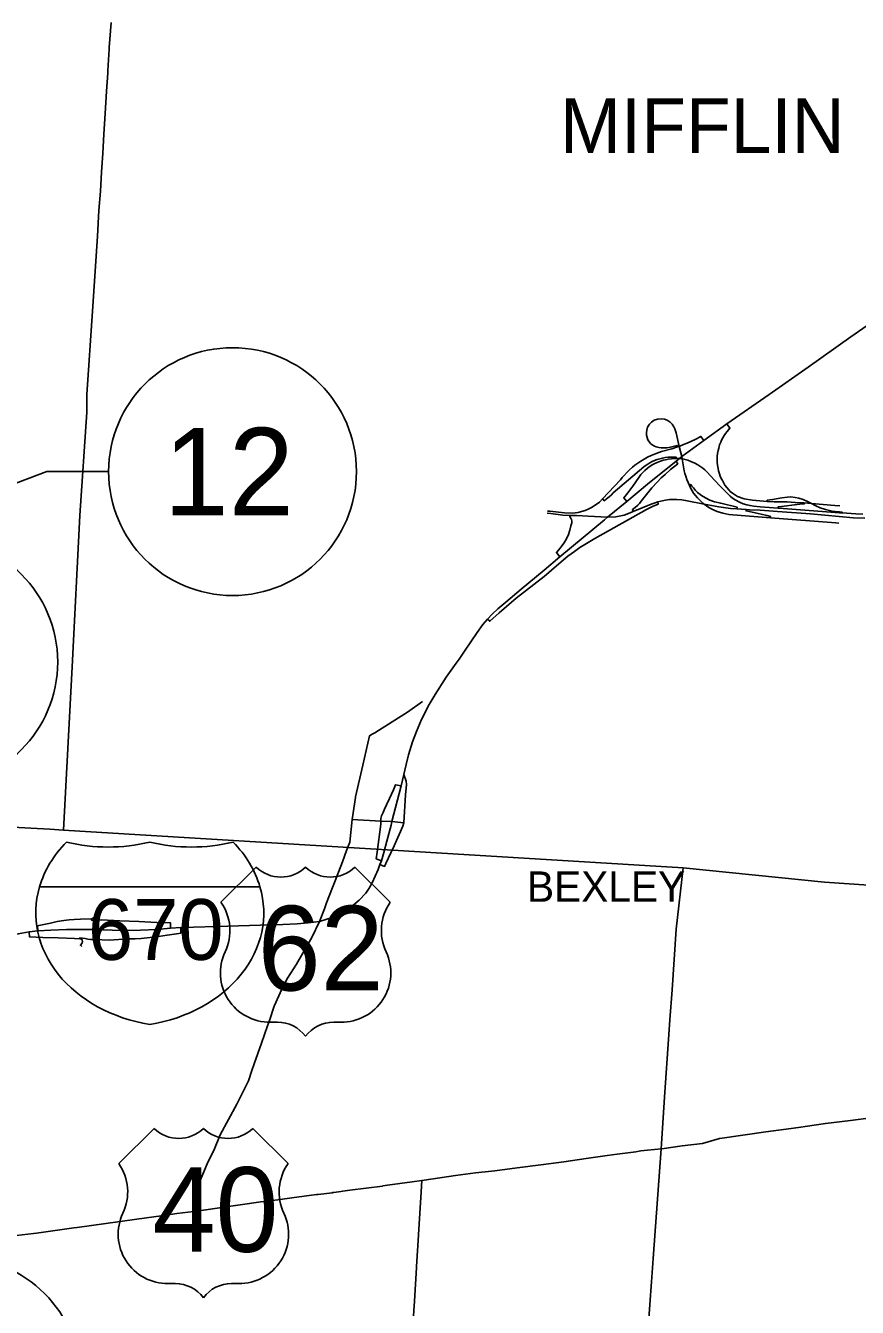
# Model space of a CAD drawing. Extents: x -1146 to -445, y -1283 to -822.
# Drawn here: x -856.5 to -822.3, y -1056.6 to -1003.9 of the extents above; entities that cross this region are included whole.
import ezdxf

# ---------------------------------------------------------------- set-up
doc = ezdxf.new("R2010")
doc.units = 0
for name, color, linetype in [('Default', 7, 'Continuous'), ('GM_X_Corporation_Text', 7, 'Continuous'), ('GM_X_Interchange_Ramps', 7, 'Continuous'), ('GM_X_Interstate_Route', 7, 'Continuous'), ('GM_X_Interstate_Shield', 7, 'Continuous'), ('GM_X_State_Route', 7, 'Continuous'), ('GM_X_Township', 7, 'Continuous'), ('GM_X_Township_Text', 7, 'Continuous'), ('GM_X_US_Route', 7, 'Continuous'), ('GM_X_US_Shield', 7, 'Continuous')]:
    doc.layers.add(name, color=color, linetype=linetype)

msp = doc.modelspace()

# ---------------------------------------------------------------- linework, layer by layer
at = {"layer": 'Default'}
msp.add_lwpolyline([(-853.091, -1022.261), (-855.638, -1022.261), (-873.197, -1028.924)], dxfattribs=at)
for centre in [(-847.997, -1022.261), (-860.28, -1030.089), (-859.326, -1059.664)]:
    msp.add_circle(centre, 5.094, dxfattribs=at)
at = {"layer": 'GM_X_Interchange_Ramps'}
for points in [[(-829.697, -1021.245), (-829.718, -1021.181), (-829.824, -1021.214), (-829.986, -1021.252), (-830.143, -1021.278), (-830.258, -1021.287), (-830.371, -1021.287), (-830.469, -1021.266), (-830.579, -1021.24), (-830.654, -1021.209), (-830.74, -1021.157), (-830.808, -1021.099), (-830.854, -1021.047), (-830.918, -1020.949), (-830.954, -1020.864), (-830.978, -1020.759), (-830.983, -1020.655), (-830.97, -1020.552), (-830.931, -1020.434), (-830.861, -1020.316), (-830.776, -1020.227), (-830.663, -1020.151), (-830.519, -1020.099), (-830.374, -1020.085), (-830.236, -1020.105), (-830.127, -1020.146), (-830.011, -1020.222), (-829.924, -1020.311), (-829.859, -1020.414), (-829.807, -1020.507), (-829.758, -1020.66), (-829.631, -1021.224), (-829.525, -1021.642), (-829.507, -1021.736), (-829.429, -1022.227), (-829.397, -1022.339), (-829.361, -1022.444), (-829.318, -1022.587), (-829.269, -1022.708), (-829.224, -1022.804), (-829.208, -1022.835), (-829.151, -1022.961), (-829.039, -1023.151), (-828.885, -1023.343), (-828.747, -1023.479), (-828.601, -1023.598), (-828.453, -1023.714), (-828.291, -1023.806), (-828.074, -1023.896), (-827.837, -1023.975), (-827.596, -1024.023), (-827.431, -1024.043), (-825.876, -1024.161), (-823.189, -1024.362), (-823.076, -1024.374)], [(-823.024, -1023.667), (-823.232, -1023.651), (-824.194, -1023.577), (-824.498, -1023.549), (-824.859, -1023.525), (-825.196, -1023.508), (-825.731, -1023.506), (-826.014, -1023.495), (-826.619, -1023.435), (-826.969, -1023.375), (-827.242, -1023.282), (-827.444, -1023.153), (-827.533, -1023.075), (-827.586, -1023.025), (-827.598, -1023.013), (-827.68, -1022.915), (-827.752, -1022.816), (-827.802, -1022.737), (-827.86, -1022.633), (-827.906, -1022.54), (-827.946, -1022.444), (-827.978, -1022.352), (-828.012, -1022.235), (-828.035, -1022.134), (-828.058, -1021.992), (-828.059, -1021.981), (-828.067, -1021.885), (-828.071, -1021.757), (-828.066, -1021.638), (-828.054, -1021.52), (-828.032, -1021.395), (-828.008, -1021.294), (-827.97, -1021.166), (-827.927, -1021.055), (-827.888, -1020.966), (-827.84, -1020.874), (-827.782, -1020.775), (-827.725, -1020.689), (-827.667, -1020.612), (-827.548, -1020.47), (-827.677, -1020.291)], [(-828.622, -1020.976), (-828.738, -1020.815), (-828.948, -1020.925), (-829.154, -1021.024), (-829.307, -1021.092), (-829.457, -1021.148), (-829.631, -1021.224), (-829.697, -1021.245), (-829.941, -1021.32), (-830.362, -1021.433), (-830.581, -1021.512), (-830.787, -1021.602), (-830.938, -1021.673), (-831.075, -1021.747), (-831.214, -1021.83), (-831.331, -1021.908), (-831.455, -1021.999), (-831.556, -1022.08), (-831.689, -1022.197), (-831.791, -1022.298), (-831.913, -1022.43), (-831.979, -1022.507), (-832.049, -1022.597), (-832.792, -1023.38), (-832.912, -1023.514), (-833.044, -1023.617), (-833.238, -1023.743), (-833.38, -1023.804), (-833.506, -1023.855), (-833.656, -1023.898), (-833.787, -1023.939), (-834.037, -1023.965), (-834.352, -1023.95), (-834.954, -1023.892), (-835.054, -1023.884)], [(-829.743, -1021.723), (-829.752, -1021.668), (-829.85, -1021.663), (-829.973, -1021.663), (-830.091, -1021.67), (-830.212, -1021.685), (-830.324, -1021.706), (-830.426, -1021.731), (-830.534, -1021.764), (-830.643, -1021.805), (-830.741, -1021.849), (-830.841, -1021.901), (-830.929, -1021.953), (-830.994, -1021.996), (-831.091, -1022.067), (-832.345, -1023.139), (-832.42, -1023.21), (-832.519, -1023.298), (-832.618, -1023.381), (-832.715, -1023.456), (-832.792, -1023.38)], [(-822.084, -1024.014), (-822.37, -1023.999), (-822.931, -1023.961), (-823.042, -1023.95), (-825.533, -1023.765), (-825.563, -1023.762), (-826.307, -1023.703), (-826.568, -1023.678), (-826.718, -1023.658), (-826.857, -1023.622), (-826.998, -1023.579), (-827.149, -1023.518), (-827.334, -1023.421), (-827.444, -1023.348), (-827.544, -1023.267), (-827.668, -1023.145), (-827.826, -1022.979), (-827.971, -1022.827), (-828.154, -1022.636), (-828.341, -1022.441), (-828.485, -1022.283), (-828.58, -1022.19), (-828.666, -1022.12), (-828.75, -1022.058), (-828.869, -1021.986), (-828.987, -1021.914), (-829.152, -1021.847), (-829.284, -1021.795), (-829.44, -1021.749), (-829.507, -1021.736), (-829.625, -1021.723), (-829.743, -1021.723), (-829.832, -1021.723), (-829.944, -1021.737), (-830.081, -1021.751), (-830.197, -1021.771), (-830.297, -1021.795), (-830.404, -1021.827), (-830.546, -1021.884), (-830.634, -1021.928), (-830.723, -1021.972), (-830.827, -1022.032), (-830.939, -1022.12), (-831.046, -1022.213), (-831.114, -1022.279), (-831.206, -1022.383), (-831.298, -1022.5), (-831.543, -1022.857), (-831.748, -1023.138), (-831.916, -1023.334), (-831.784, -1023.485)], [(-831.525, -1023.907), (-831.557, -1023.824), (-831.449, -1023.742), (-831.339, -1023.641), (-831.272, -1023.57), (-831.195, -1023.477), (-830.754, -1022.922), (-830.542, -1022.692), (-830.376, -1022.523), (-830.216, -1022.378), (-829.986, -1022.178), (-829.691, -1021.938), (-829.758, -1021.831)], [(-829.208, -1022.835), (-829.159, -1022.796), (-829.113, -1022.854), (-829.048, -1022.929), (-828.961, -1023.031), (-828.876, -1023.116), (-828.718, -1023.238), (-828.551, -1023.344), (-828.379, -1023.429), (-828.188, -1023.498), (-827.928, -1023.561), (-827.257, -1023.717), (-827.27, -1023.795)], [(-835.059, -1023.967), (-834.913, -1023.982), (-834.418, -1024.047), (-834.126, -1024.06), (-833.852, -1024.067), (-833.377, -1024.094), (-832.849, -1024.126), (-832.582, -1024.136), (-832.242, -1024.121), (-831.892, -1024.057), (-831.712, -1023.99), (-831.525, -1023.907), (-831.154, -1023.748), (-830.783, -1023.596), (-830.624, -1023.541), (-830.514, -1023.508), (-830.391, -1023.478), (-830.191, -1023.431), (-830.029, -1023.412), (-829.873, -1023.402), (-829.725, -1023.412), (-829.526, -1023.42), (-829.304, -1023.463), (-828.601, -1023.598), (-828.01, -1023.708), (-827.531, -1023.778), (-827.27, -1023.795), (-826.878, -1023.821), (-826.739, -1023.83), (-826.303, -1023.852), (-825.592, -1023.896), (-824.234, -1023.995), (-823.053, -1024.112), (-822.463, -1024.155), (-822.001, -1024.177)], [(-822.931, -1023.961), (-822.931, -1023.934), (-823.04, -1023.921), (-823.224, -1023.9), (-823.339, -1023.883), (-823.613, -1023.813), (-823.834, -1023.744), (-824.021, -1023.672), (-824.194, -1023.577), (-824.355, -1023.493), (-824.537, -1023.413), (-824.716, -1023.353), (-824.87, -1023.323), (-825.038, -1023.304), (-825.186, -1023.306), (-825.41, -1023.334), (-825.796, -1023.413), (-826.011, -1023.439), (-826.014, -1023.495)], [(-837.514, -1028.325), (-837.417, -1028.411), (-837.041, -1028.066), (-836.338, -1027.47), (-835.189, -1026.568), (-834.582, -1026.053), (-834.213, -1025.743), (-833.941, -1025.545), (-833.713, -1025.387), (-833.098, -1025.016), (-830.973, -1023.824), (-830.732, -1023.699), (-830.496, -1023.595), (-830.514, -1023.508)], [(-826.878, -1023.821), (-826.884, -1023.876), (-826.754, -1023.896), (-826.508, -1023.953), (-826.264, -1024.012), (-826.034, -1024.072), (-825.876, -1024.107), (-825.876, -1024.161)], [(-824.498, -1023.549), (-824.495, -1023.586), (-824.68, -1023.6), (-824.786, -1023.609), (-825.423, -1023.691), (-825.561, -1023.704), (-825.563, -1023.762)], [(-834.126, -1024.06), (-834.127, -1024.12), (-834.087, -1024.175), (-834.064, -1024.23), (-834.053, -1024.283), (-834.053, -1024.364), (-834.09, -1024.488), (-834.136, -1024.673), (-834.185, -1024.84), (-834.277, -1025.052), (-834.381, -1025.21), (-834.527, -1025.406), (-834.685, -1025.592), (-834.541, -1025.761)], [(-841.07, -1035.186), (-841.297, -1035.136), (-841.384, -1035.346), (-841.539, -1035.697), (-841.666, -1035.958), (-841.752, -1036.139), (-841.809, -1036.283), (-841.868, -1036.413), (-841.902, -1036.525), (-841.899, -1036.629)], [(-841.899, -1036.629), (-841.905, -1036.756), (-842.052, -1037.903), (-842.088, -1038.183), (-841.879, -1038.272)], [(-841.938, -1038.412), (-841.747, -1038.493), (-841.691, -1038.373), (-841.489, -1037.932), (-841.356, -1037.643), (-841, -1036.839), (-840.949, -1036.702)], [(-853.408, -1040.334), (-853.471, -1040.326), (-853.525, -1040.425), (-853.593, -1040.534), (-853.66, -1040.584), (-853.738, -1040.626), (-853.788, -1040.644), (-854.252, -1040.659), (-854.514, -1040.674), (-854.709, -1040.688), (-854.94, -1040.72), (-855.206, -1040.762), (-855.486, -1040.826), (-855.957, -1040.922), (-856.011, -1040.933), (-855.997, -1041.15)], [(-853.515, -1040.706), (-853.625, -1040.704), (-853.8, -1040.704), (-853.788, -1040.644)], [(-850.548, -1041.038), (-850.551, -1040.813), (-851.117, -1040.798), (-851.854, -1040.755), (-852.628, -1040.731), (-853.381, -1040.695), (-853.515, -1040.706)], [(-856.357, -1041.184), (-856.342, -1041.396), (-855.795, -1041.424), (-855.171, -1041.436), (-854.491, -1041.464), (-854.275, -1041.474), (-854.214, -1041.484), (-854.195, -1041.503), (-854.181, -1041.525), (-854.175, -1041.55), (-854.17, -1041.571), (-854.171, -1041.596), (-854.174, -1041.621), (-854.184, -1041.65), (-854.195, -1041.67), (-854.252, -1041.738), (-854.188, -1041.782)], [(-853.944, -1041.487), (-853.843, -1041.494), (-853.662, -1041.504), (-853.076, -1041.522), (-852.284, -1041.479), (-851.996, -1041.472), (-851.752, -1041.454), (-851.511, -1041.433), (-851.269, -1041.401), (-851.046, -1041.376), (-850.688, -1041.319), (-850.205, -1041.252), (-850.119, -1041.236), (-850.119, -1041.091), (-850.119, -1041.011)], [(-854.275, -1041.474), (-854.28, -1041.434), (-854.064, -1041.46), (-853.944, -1041.487)]]:
    msp.add_lwpolyline(points, dxfattribs=at)
at = {"layer": 'GM_X_Interstate_Route'}
for points in [[(-832.702, -1024.238), (-832.582, -1024.136), (-831.784, -1023.485), (-830.941, -1022.774), (-829.758, -1021.831), (-829.625, -1021.723), (-829.525, -1021.642), (-828.622, -1020.976), (-827.677, -1020.291), (-825.937, -1019.089), (-824.334, -1017.972), (-822.58, -1016.719), (-821.586, -1016.03)], [(-835.183, -1026.313), (-834.541, -1025.761), (-832.702, -1024.238)], [(-838.682, -1029.97), (-838.456, -1029.639), (-837.942, -1028.871), (-837.703, -1028.541), (-837.514, -1028.325), (-837.324, -1028.118), (-837.089, -1027.9), (-836.767, -1027.624), (-836.126, -1027.091), (-835.183, -1026.313)], [(-840.951, -1034.72), (-840.856, -1034.299), (-840.758, -1033.904), (-840.595, -1033.375), (-840.44, -1032.944), (-840.222, -1032.457), (-839.911, -1031.843), (-839.668, -1031.427), (-839.213, -1030.709), (-838.801, -1030.144), (-838.682, -1029.97)], [(-841.482, -1036.799), (-841.444, -1036.653), (-841.07, -1035.186), (-840.951, -1034.72)], [(-844.423, -1040.756), (-843.906, -1040.591), (-843.572, -1040.438), (-843.299, -1040.291), (-843.145, -1040.184), (-842.788, -1039.878), (-842.518, -1039.59), (-842.375, -1039.39), (-842.257, -1039.176), (-842.011, -1038.62), (-841.938, -1038.412), (-841.879, -1038.272), (-841.782, -1037.917), (-841.654, -1037.451), (-841.482, -1036.799)], [(-858.019, -1041.515), (-857.96, -1041.502), (-857.276, -1041.349), (-856.807, -1041.271), (-856.357, -1041.184), (-855.997, -1041.15), (-855.473, -1041.118), (-854.824, -1041.092), (-854.068, -1041.087), (-853.699, -1041.094), (-852.582, -1041.126), (-851.776, -1041.122), (-851.115, -1041.087), (-850.548, -1041.038), (-850.119, -1041.011), (-850.071, -1041.006), (-848.187, -1040.957), (-846.857, -1040.916), (-845.935, -1040.885), (-845.341, -1040.858), (-844.894, -1040.818), (-844.423, -1040.756)]]:
    msp.add_lwpolyline(points, dxfattribs=at)
at = {"layer": 'GM_X_Interstate_Shield'}
msp.add_line((-846.869, -1039.33), (-855.934, -1039.33), dxfattribs=at)
msp.add_line((-846.869, -1039.33), (-855.934, -1039.33), dxfattribs=at)
for centre, start_param, end_param in [((-850.229, -1040.402), 2.47259, 2.911027), ((-853.114, -1033.011), 4.415841, 5.008937), ((-849.689, -1033.011), 4.415841, 5.008937), ((-852.573, -1040.402), 0.230566, 0.669003), ((-850.229, -1040.402), 2.911027, 4.511031), ((-852.573, -1040.402), 4.913747, 6.513751)]:
    msp.add_ellipse(centre, major_axis=(5.859, 0), ratio=0.8, start_param=start_param, end_param=end_param, dxfattribs=at)
at = {"layer": 'GM_X_State_Route'}
for points in [[(-830.348, -1050.11), (-829.516, -1049.991), (-828.669, -1049.885), (-827.982, -1049.684), (-827.873, -1049.668), (-826.066, -1049.414), (-825.231, -1049.296), (-824.637, -1049.213), (-824.453, -1049.186), (-823.621, -1049.067), (-822.586, -1048.939), (-821.759, -1048.836), (-820.793, -1048.717), (-819.872, -1048.593), (-818.884, -1048.461), (-818.043, -1048.362), (-816.988, -1048.237), (-816.987, -1048.237)], [(-840.213, -1051.416), (-839.752, -1051.344), (-838.833, -1051.201), (-838.012, -1051.101), (-837.21, -1051.015), (-836.296, -1050.889), (-835.322, -1050.765), (-834.376, -1050.64), (-833.456, -1050.509), (-832.601, -1050.385), (-832.181, -1050.324), (-831.42, -1050.229), (-831.211, -1050.196), (-830.376, -1050.114), (-830.348, -1050.11)]]:
    msp.add_lwpolyline(points, dxfattribs=at)
at = {"layer": 'GM_X_Township'}
msp.add_line((-854.945, -1037.008), (-829.476, -1038.559), dxfattribs=at)
for points in [[(-852.989, -1003.797), (-853.066, -1004.818), (-853.066, -1004.895), (-853.121, -1005.763), (-853.132, -1005.878), (-853.183, -1006.624), (-853.231, -1007.533), (-853.296, -1008.381), (-853.335, -1009.164), (-853.387, -1009.948), (-853.433, -1010.732), (-853.492, -1011.521), (-853.549, -1012.577), (-853.756, -1015.667), (-853.99, -1019.089), (-853.994, -1019.823), (-854.283, -1024.069), (-854.592, -1030.288), (-854.945, -1037.008), (-855.508, -1036.967), (-856.295, -1036.918), (-858.266, -1036.807)], [(-830.982, -1058.489), (-830.845, -1056.503), (-830.772, -1055.58), (-830.709, -1054.616), (-830.376, -1050.114), (-830.241, -1047.987), (-830.061, -1045.409), (-830.016, -1044.798), (-829.926, -1043.572), (-829.753, -1041.071), (-829.476, -1038.559), (-823.661, -1039.144), (-804.051, -1040.471), (-802.831, -1040.571), (-802.093, -1040.628), (-794.786, -1041.185), (-793.926, -1041.236), (-792.83, -1041.284), (-792.543, -1041.281), (-782.508, -1042.001)]]:
    msp.add_lwpolyline(points, dxfattribs=at)
at = {"layer": 'GM_X_US_Route'}
for points in [[(-842.253, -1033.063), (-842.227, -1033.049), (-842.147, -1033.001), (-841.439, -1032.553), (-840.8, -1032.148), (-840.184, -1031.707)], [(-849.584, -1052.685), (-849.517, -1052.292), (-849.44, -1051.695), (-849.383, -1051.541), (-849.012, -1050.659), (-848.769, -1050.172), (-848.508, -1049.536), (-847.828, -1048.272), (-847.487, -1047.614), (-847.336, -1047.312), (-847.2, -1046.893), (-847.107, -1046.611), (-846.809, -1045.756), (-846.557, -1045.052), (-846.484, -1044.837), (-846.284, -1044.248), (-845.973, -1043.54), (-845.738, -1043.089), (-845.368, -1042.508), (-844.741, -1041.419), (-844.423, -1040.756), (-844.22, -1040.233), (-844.128, -1039.996), (-843.884, -1039.365), (-843.748, -1039.016), (-843.733, -1038.975), (-843.48, -1038.3), (-843.306, -1037.837), (-843.181, -1037.502), (-843.082, -1036.569), (-842.943, -1035.658), (-842.939, -1035.633), (-842.647, -1034.325), (-842.363, -1033.12), (-842.253, -1033.063)], [(-840.949, -1036.702), (-840.883, -1035.553), (-840.852, -1035.127), (-840.856, -1034.994), (-840.951, -1034.72)], [(-843.082, -1036.569), (-841.899, -1036.629), (-841.444, -1036.653), (-840.949, -1036.702)], [(-843.828, -1051.901), (-843.174, -1051.814), (-841.831, -1051.636), (-841.821, -1051.635), (-841.62, -1051.607), (-840.61, -1051.47), (-840.213, -1051.416)], [(-840.213, -1051.416), (-840.242, -1051.873), (-840.353, -1053.649)], [(-848.538, -1052.535), (-846.834, -1052.292), (-846.132, -1052.199), (-845.554, -1052.122), (-844.545, -1051.988), (-844.475, -1051.98), (-843.899, -1051.91), (-843.871, -1051.907), (-843.833, -1051.902), (-843.828, -1051.901)], [(-854.383, -1053.338), (-852.028, -1053.018), (-851.534, -1052.948), (-850.938, -1052.864), (-850.29, -1052.773), (-849.584, -1052.685)], [(-849.584, -1052.685), (-849.191, -1052.629)], [(-849.191, -1052.629), (-849.191, -1052.629), (-848.538, -1052.535)], [(-857.469, -1053.751), (-856.881, -1053.676), (-856.184, -1053.586), (-856.06, -1053.57), (-854.517, -1053.356), (-854.384, -1053.338), (-854.383, -1053.338)], [(-840.353, -1053.649), (-840.353, -1053.653), (-840.434, -1054.946), (-840.437, -1054.988), (-840.522, -1056.368), (-840.609, -1057.775), (-840.611, -1057.807), (-840.692, -1058.713), (-840.694, -1058.754), (-840.748, -1059.66), (-840.803, -1060.594), (-840.804, -1060.616), (-840.822, -1060.906), (-840.844, -1061.266)]]:
    msp.add_lwpolyline(points, dxfattribs=at)
at = {"layer": 'GM_X_US_Shield'}
for p, q in [((-847.024, -1038.52), (-848.474, -1039.97)), ((-841.513, -1039.97), (-842.964, -1038.52)), ((-846.444, -1044.901), (-846.154, -1044.901)), ((-843.834, -1044.901), (-843.544, -1044.901)), ((-851.226, -1049.267), (-852.676, -1050.717)), ((-845.715, -1050.717), (-847.166, -1049.267)), ((-850.646, -1055.648), (-850.356, -1055.648)), ((-848.036, -1055.648), (-847.746, -1055.648))]:
    msp.add_line(p, q, dxfattribs=at)
for centre, radius, start, end in [((-846.009, -1037.484), 1.45, 225.573, 314.427), ((-843.979, -1037.484), 1.45, 225.573, 314.427), ((-850.137, -1041.134), 2.03, 334.5471, 35.0009), ((-839.85, -1041.134), 2.03, 144.9991, 205.4529), ((-846.467, -1042.87), 2.03, 154.8319, 270.6383), ((-843.521, -1042.87), 2.03, 269.3617, 25.1681), ((-846.154, -1046.351), 1.45, 36.8699, 90), ((-843.834, -1046.351), 1.45, 90, 143.1301), ((-850.211, -1048.231), 1.45, 225.573, 314.427), ((-848.181, -1048.231), 1.45, 225.573, 314.427), ((-854.339, -1051.881), 2.03, 334.5471, 35.0009), ((-844.052, -1051.881), 2.03, 144.9991, 205.4529), ((-850.669, -1053.617), 2.03, 154.8319, 270.6383), ((-847.723, -1053.617), 2.03, 269.3617, 25.1681), ((-850.356, -1057.098), 1.45, 36.8699, 90), ((-848.036, -1057.098), 1.45, 90, 143.1301)]:
    msp.add_arc(centre, radius, start, end, dxfattribs=at)

# ---------------------------------------------------------------- texts
at = {"layer": 'Default'}
msp.add_text('12', height=3.6, dxfattribs=at).set_placement((-850.831, -1024.061))
at = {"layer": 'GM_X_Corporation_Text'}
msp.add_text('BEXLEY', height=1.25, rotation=0, dxfattribs=at).set_placement((-835.891, -1039.951))
at = {"layer": 'GM_X_Interstate_Shield'}
msp.add_text('670', height=2.5, dxfattribs=at).set_placement((-853.942, -1042.338))
at = {"layer": 'GM_X_Township_Text'}
msp.add_text('MIFFLIN', height=2.25, rotation=0, dxfattribs=at).set_placement((-834.537, -1009.16))
at = {"layer": 'GM_X_US_Shield'}
for s, p in [('62', (-846.964, -1043.595)), ('40', (-851.287, -1054.342))]:
    msp.add_text(s, height=3.4805, dxfattribs=at).set_placement(p)

doc.saveas('drawing.dxf')
